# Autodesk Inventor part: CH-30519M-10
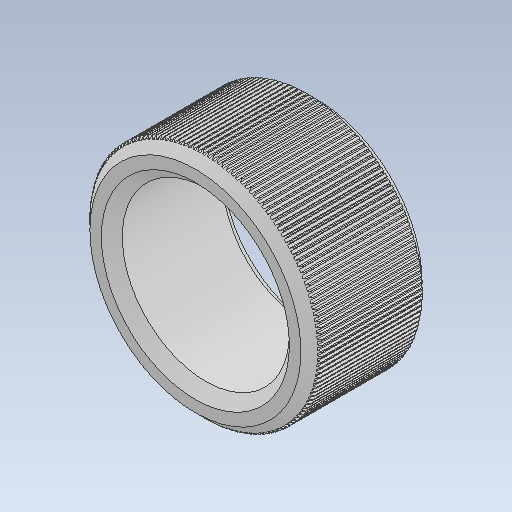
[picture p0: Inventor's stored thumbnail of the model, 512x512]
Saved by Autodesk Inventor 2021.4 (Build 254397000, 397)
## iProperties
Created: 2017-11
Part Number: CH-30519M-10
Material: Ogólny
Document SubType Name: Modeling
Designer: user
Density: 1 g/cm^3
Appearance: Domyślna
Author: user
Revision Number: ÈÎºÎ
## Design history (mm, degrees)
feature "ÕóÁÐ(Ô²ÖÜ)1"
node "Bryła1"
